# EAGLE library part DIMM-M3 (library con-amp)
AMP connector
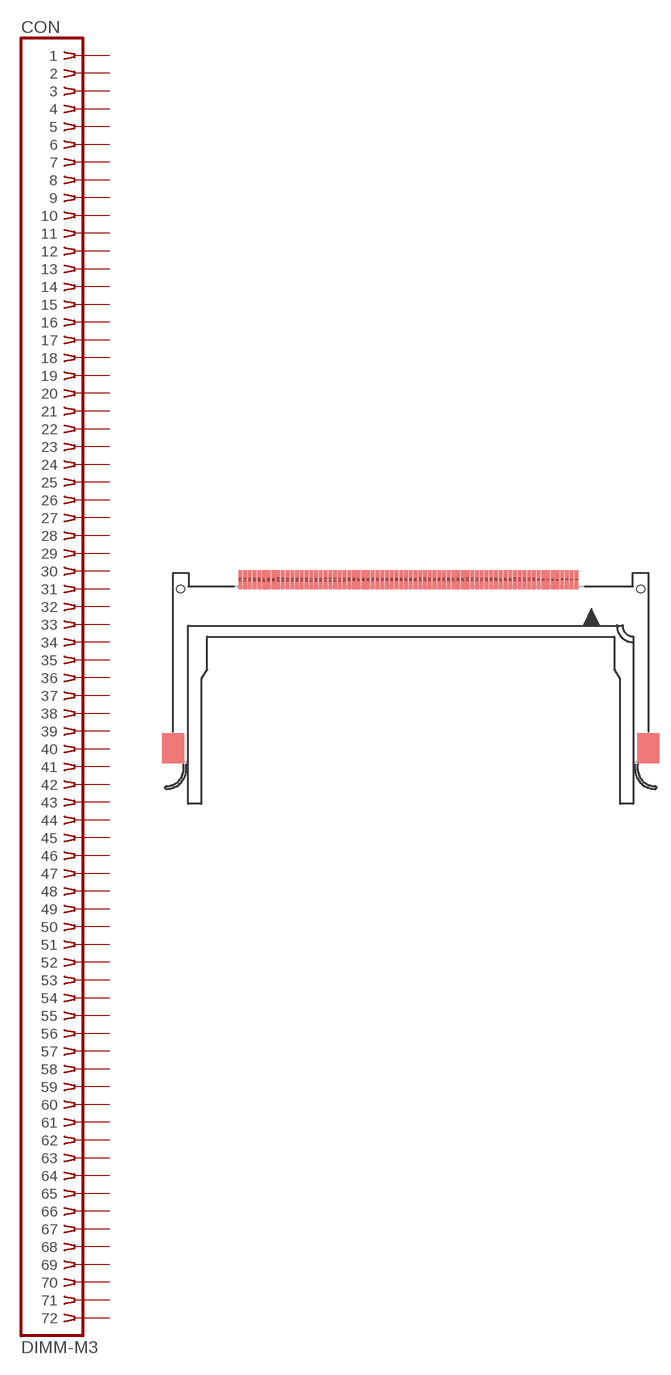
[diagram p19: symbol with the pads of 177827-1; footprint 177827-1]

Designator prefix CON

## DIMM-M3 (MPN: 177827-1; OC_FARNELL: unknown; OC_NEWARK: 17R5432)  [177827-1]
1  1  pas
2  2  pas
3  3  pas
4  4  pas
5  5  pas
6  6  pas
7  7  pas
8  8  pas
9  9  pas
10  10  pas
11  11  pas
12  12  pas
13  13  pas
14  14  pas
15  15  pas
16  16  pas
17  17  pas
18  18  pas
19  19  pas
20  20  pas
21  21  pas
22  22  pas
23  23  pas
24  24  pas
25  25  pas
26  26  pas
27  27  pas
28  28  pas
29  29  pas
30  30  pas
31  31  pas
32  32  pas
33  33  pas
34  34  pas
35  35  pas
36  36  pas
37  37  pas
38  38  pas
39  39  pas
40  40  pas
41  41  pas
42  42  pas
43  43  pas
44  44  pas
45  45  pas
46  46  pas
47  47  pas
48  48  pas
49  49  pas
50  50  pas
51  51  pas
52  52  pas
53  53  pas
54  54  pas
55  55  pas
56  56  pas
57  57  pas
58  58  pas
59  59  pas
60  60  pas
61  61  pas
62  62  pas
63  63  pas
64  64  pas
65  65  pas
66  66  pas
67  67  pas
68  68  pas
69  69  pas
70  70  pas
71  71  pas
72  72  pas

## Footprint 177827-1 (pad centres in mm)
DIMM Mini Memory Module M3
smd 0.508 x 2.54: 1 22.225,1.27; 2 21.59,1.27; 3 20.955,1.27; 4 20.32,1.27; 5 19.685,1.27; 6 19.05,1.27; 7 18.415,1.27; 8 17.78,1.27; 9 17.145,1.27; 10 16.51,1.27; 11 15.875,1.27; 12 15.24,1.27; 13 14.605,1.27; 14 13.97,1.27; 15 13.335,1.27; 16 12.7,1.27; 17 12.065,1.27; 18 11.43,1.27; 19 10.795,1.27; 20 10.16,1.27; 21 9.525,1.27; 22 8.89,1.27; 23 8.255,1.27; 24 7.62,1.27; 25 6.985,1.27; 26 6.35,1.27; 27 5.715,1.27; 28 5.08,1.27; 29 4.445,1.27; 30 3.81,1.27; 31 3.175,1.27; 32 2.54,1.27; 33 1.905,1.27; 34 1.27,1.27; 35 0.635,1.27; 36 0,1.27; 37 -0.635,1.27; 38 -1.27,1.27; 39 -1.905,1.27; 40 -2.54,1.27; 41 -3.175,1.27; 42 -3.81,1.27; 43 -4.445,1.27; 44 -5.08,1.27; 45 -5.715,1.27; 46 -6.35,1.27; 47 -6.985,1.27; 48 -7.62,1.27; 49 -8.255,1.27; 50 -8.89,1.27; 51 -9.525,1.27; 52 -10.16,1.27; 53 -10.795,1.27; 54 -11.43,1.27; 55 -12.065,1.27; 56 -12.7,1.27; 57 -13.335,1.27; 58 -13.97,1.27; 59 -14.605,1.27; 60 -15.24,1.27; 61 -15.875,1.27; 62 -16.51,1.27; 63 -17.145,1.27; 64 -17.78,1.27; 65 -18.415,1.27; 66 -19.05,1.27; 67 -19.685,1.27; 68 -20.32,1.27; 69 -20.955,1.27; 70 -21.59,1.27; 71 -22.225,1.27; 72 -22.86,1.27
hole 1.016 at -30.861,0
hole 1.016 at 30.861,0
